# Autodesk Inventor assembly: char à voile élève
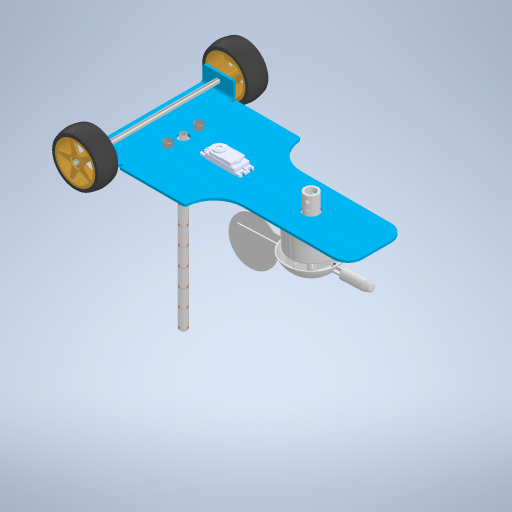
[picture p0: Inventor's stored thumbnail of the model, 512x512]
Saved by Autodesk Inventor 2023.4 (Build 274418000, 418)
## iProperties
Created: 2023-11
Part Number: char à voile élève
Document SubType Name: Assembly
Designer: mel
Author: mel
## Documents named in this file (5)
- D:\travail\année 2023-2024\IT\char à voile\char à voile élève.iam
- D:\travail\année 2023-2024\IT\char à voile\classe char.iam
- D:\travail\année 2023-2024\IT\char à voile\classe voile.iam
- D:\travail\année 2023-2024\IT\char à voile\girouette partie mobile.iam
- D:\travail\année 2023-2024\IT\char à voile\classe roue bh.iam
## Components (5 placed, 4 different names)
1. classe char:1 [sub-assembly] — Logement:3, Logement:5, Logement:6, Logement:7
2. classe voile:1 [sub-assembly] — Logement:3
3. girouette partie mobile:1 [sub-assembly] — Logement:5
4. classe roue bh:1 [sub-assembly] — Logement:6
5. classe roue bh:2 [sub-assembly] — Logement:7
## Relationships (4: Insert 4)
- Logement:3 [Insert]: classe char:1 ↔ classe voile:1
- Logement:5 [Insert]: classe char:1 ↔ girouette partie mobile:1
- Logement:6 [Insert]: classe char:1 ↔ classe roue bh:1
- Logement:7 [Insert]: classe char:1 ↔ classe roue bh:2
